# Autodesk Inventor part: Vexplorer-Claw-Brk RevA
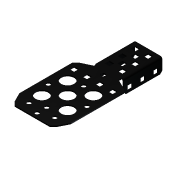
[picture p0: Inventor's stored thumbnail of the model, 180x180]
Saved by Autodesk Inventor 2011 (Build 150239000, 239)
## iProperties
Created: 2007-10
Part Number: Vexplorer-Claw-Brk RevA
Document SubType Name: Modeling
Material: Aluminum-6061-AHC
Density: 2.71 g/cm^3
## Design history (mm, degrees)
feature "Base1"
sketch "Sketch1" dims "d13" = 25.4
  geometry: L1 (-3.175, 3.175)-(-7.937, 12.7) reference; L2 (-3.175, 3.175)-(0, 0) reference; L3 (0, 0)-(34.925, 0) reference; L4 (38.1, 3.175)-(34.925, 0) reference; L5 (38.1, 3.175)-(42.863, 12.7) reference; L6 (42.863, 12.7)-(42.862, 65.013) reference; L7 (39.688, 68.188)-(42.862, 65.013) reference; L8 (39.688, 68.188)-(29.54, 73.025) reference; L9 (29.54, 73.025)-(29.54, 76.2) reference; L10 (29.54, 76.2)-(29.54, 114.3) reference; L11 (29.54, 114.3)-(5.385, 114.3) reference; L12 (5.385, 114.3)-(5.385, 76.2) reference; L13 (5.385, 76.2)-(5.385, 73.025) reference; L14 (-4.763, 68.188)-(5.385, 73.025) reference; L15 (-4.763, 68.188)-(-7.937, 65.013) reference; L16 (-7.937, 12.7)-(-7.937, 65.013) reference; L17 (19.774, 99.289)-(19.774, 103.911) reference; L18 (15.151, 99.289)-(19.774, 99.289) reference; L19 (15.151, 103.911)-(15.151, 99.289) reference; L20 (19.774, 103.911)-(15.151, 103.911) reference; L21 (13.424, 105.639)-(13.424, 110.261) reference; L22 (8.801, 105.639)-(13.424, 105.639) reference; L23 (8.801, 110.261)-(8.801, 105.639) reference; L24 (13.424, 110.261)-(8.801, 110.261) reference; L25 (26.124, 105.639)-(26.124, 110.261) reference; L26 (21.501, 105.639)-(26.124, 105.639) reference; L27 (21.501, 110.261)-(21.501, 105.639) reference; L28 (26.124, 110.261)-(21.501, 110.261) reference; L29 (26.124, 58.014)-(26.124, 62.636) reference; L30 (21.501, 58.014)-(26.124, 58.014) reference; L31 (21.501, 62.636)-(21.501, 58.014) reference; L32 (26.124, 62.636)-(21.501, 62.636) reference; L33 (38.824, 58.014)-(38.824, 62.636) reference; L34 (34.201, 58.014)-(38.824, 58.014) reference; L35 (34.201, 62.636)-(34.201, 58.014) reference; L36 (38.824, 62.636)-(34.201, 62.636) reference; L37 (13.424, 58.014)-(13.424, 62.636) reference; L38 (8.801, 58.014)-(13.424, 58.014) reference; L39 (8.801, 62.636)-(8.801, 58.014) reference; L40 (13.424, 62.636)-(8.801, 62.636) reference; L41 (0.724, 58.014)-(0.724, 62.636) reference; L42 (-3.899, 58.014)-(0.724, 58.014) reference; L43 (-3.899, 62.636)-(-3.899, 58.014) reference; L44 (0.724, 62.636)-(-3.899, 62.636) reference; L45 (26.124, 92.939)-(26.124, 97.561) reference; L46 (21.501, 92.939)-(26.124, 92.939) reference; L47 (21.501, 97.561)-(21.501, 92.939) reference; L48 (26.124, 97.561)-(21.501, 97.561) reference; L49 (13.424, 92.939)-(13.424, 97.561) reference; L50 (8.801, 92.939)-(13.424, 92.939) reference; L51 (8.801, 97.561)-(8.801, 92.939) reference; L52 (13.424, 97.561)-(8.801, 97.561) reference; L53 (26.124, 80.239)-(26.124, 84.861) reference; L54 (21.501, 80.239)-(26.124, 80.239) reference; L55 (21.501, 84.861)-(21.501, 80.239) reference; L56 (26.124, 84.861)-(21.501, 84.861) reference; L57 (13.424, 80.239)-(13.424, 84.861) reference; L58 (8.801, 80.239)-(13.424, 80.239) reference; L59 (8.801, 84.861)-(8.801, 80.239) reference; L60 (13.424, 84.861)-(8.801, 84.861) reference; L61 (19.774, 86.589)-(19.774, 91.211) reference; L62 (15.151, 86.589)-(19.774, 86.589) reference; L63 (15.151, 91.211)-(15.151, 86.589) reference; L64 (19.774, 91.211)-(15.151, 91.211) reference; C1 r 6.35 at (30.163, 47.625) reference; C2 r 6.35 at (4.763, 47.625) reference; C3 r 6.35 at (4.763, 22.225) reference; C4 r 6.35 at (30.163, 22.225) reference; C5 r 6.35 at (17.463, 34.925) reference; C6 r 2.07 at (17.463, 69.85) reference; C7 r 2.07 at (17.463, 50.8) reference; C8 r 2.07 at (17.463, 14.287) reference; C9 r 2.07 at (17.463, 4.762) reference; C10 r 2.07 at (4.763, 9.525) reference; C11 r 2.07 at (30.163, 9.525) reference; C12 r 2.07 at (-1.588, 34.925) reference; C13 r 2.07 at (36.513, 34.925) reference; C14 r 2.311 at (11.113, 107.95); C15 r 2.311 at (11.113, 95.25); C16 r 2.311 at (11.113, 82.55); C17 r 2.311 at (23.813, 107.95); C18 r 2.311 at (23.813, 95.25); C19 r 2.311 at (23.813, 82.55); C20 r 2.311 at (-1.587, 60.325); C21 r 2.311 at (11.113, 60.325); C22 r 2.311 at (23.813, 60.325); C23 r 2.311 at (36.513, 60.325)
  constraints: 10 centre point, 8 tangent, 2 horizontal, 1 vertical, 16 other
  dimensions: "d2" = 12.7 distance of C14.centre C15.centre; "d5" = 12.7 distance of C14.centre C17.centre; "d10" = 12.7 distance of C20.centre C21.centre
workpoint "Work Point1"
body "Solid1"
